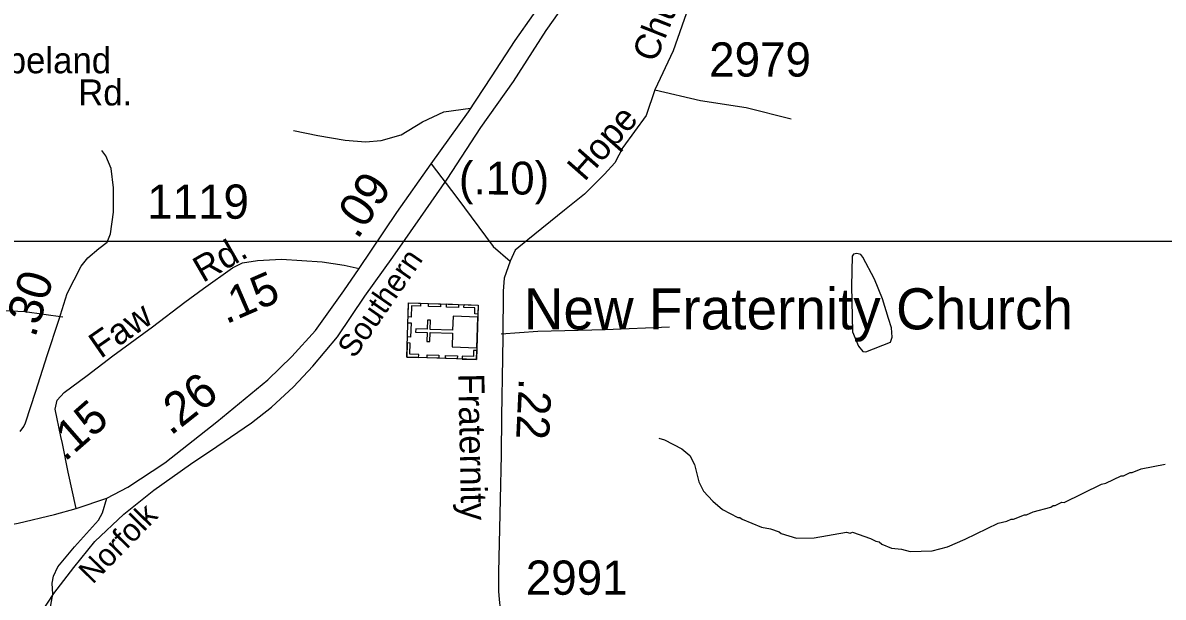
# Model space of a CAD drawing. Extents: x 1547597 to 1699558, y 810033 to 920809.
# Drawn here: x 1601176 to 1605342, y 830007 to 832105 of the extents above; entities that cross this region are included whole.
import ezdxf

# ---------------------------------------------------------------- set-up
doc = ezdxf.new("R2010")
doc.units = 0
for name, color, linetype in [('Exist Cultural Church with Cemetery CELL', 7, 'Continuous'), ('Exist Cultural Church with Cemetery Label', 7, 'Continuous'), ('Exist Hydrographic Misc Water Feature', 7, 'Continuous'), ('Exist Railroad Mainline', 7, 'Continuous'), ('Exist Railroad Mainline Label', 7, 'Continuous'), ('Exist Road Non-System Type 51', 7, 'Continuous'), ('Exist Road Primary US Mileage Hundredths English Label', 7, 'Continuous'), ('Exist Road Primary US UnDivided 4 Lane Attributed', 7, 'Continuous'), ('Exist Road Secondary Mileage Hundredths English Label', 7, 'Continuous'), ('Exist Road Secondary Type 41 Attributed', 7, 'Continuous'), ('Exist Road Secondary Type 51 Attributed', 7, 'Continuous'), ('Exist Road Secondary Type 51 Label', 7, 'Continuous'), ('Exist Road Secondary Type 51 Number Label', 7, 'Continuous'), ('Map Preparation Inset Cut Line', 7, 'Continuous')]:
    doc.layers.add(name, color=color, linetype=linetype)

msp = doc.modelspace()

# ---------------------------------------------------------------- linework, layer by layer
at = {"layer": 'Exist Cultural Church with Cemetery CELL'}
for points in [[(1602578.8, 830883.5), (1602585.4, 831082.5), (1602839.9, 831074), (1602833.2, 830875)], [(1602628.7, 831081.1), (1602628.4, 831069.8), (1602596.2, 831070.8), (1602594.8, 831030.3), (1602583.7, 831030.7), (1602585.4, 831082.5)], [(1602701.4, 831067.3), (1602658.1, 831068.7), (1602658.5, 831080.1), (1602701.8, 831078.7)], [(1602767.3, 831065), (1602724, 831066.5), (1602724.4, 831077.9), (1602767.7, 831076.4)], [(1602838.8, 831040.9), (1602827.3, 831041.3), (1602828, 831063.3), (1602787.6, 831064.6), (1602788, 831075.7), (1602839.9, 831074)], [(1602834.6, 830918.1), (1602838.4, 831030.2), (1602747.9, 831033.2), (1602746.2, 830982.5), (1602664.7, 830985.2), (1602665.8, 831018.2), (1602654.8, 831018.5), (1602653.7, 830985.6), (1602611.5, 830987), (1602611.1, 830975.4), (1602653.3, 830973.9), (1602652.2, 830940.9), (1602663.2, 830940.5), (1602664.3, 830973.6), (1602745.8, 830970.9), (1602744.1, 830921.1)], [(1602581.2, 830957.5), (1602583, 831009.3), (1602594.4, 831009), (1602592.6, 830957.2)], [(1602622, 830882.1), (1602622.4, 830893.4), (1602590.2, 830894.5), (1602591.6, 830935), (1602580.5, 830935.4), (1602578.8, 830883.5)], [(1602834.3, 830908.1), (1602822.8, 830908.5), (1602822.1, 830886.5), (1602781.7, 830887.8), (1602781.3, 830876.7), (1602833.2, 830875)], [(1602696.2, 830879.6), (1602652.9, 830881), (1602653.3, 830892.4), (1602696.5, 830891)], [(1602763.3, 830877.3), (1602720.1, 830878.8), (1602720.4, 830890.1), (1602763.7, 830888.7)]]:
    msp.add_lwpolyline(points, close=True, dxfattribs=at)
at = {"layer": 'Exist Hydrographic Misc Water Feature'}
for points in [[(1604207.3, 830976), (1604228.7, 830923.3), (1604244.9, 830904.5), (1604255.7, 830902.7), (1604345.6, 830937.8), (1604351.9, 830956.3), (1604349, 830990.8), (1604339, 831025.3), (1604316.8, 831096.1), (1604287, 831168.6), (1604244.8, 831249.4), (1604237.2, 831258.7), (1604222.5, 831262.2), (1604211, 831260.1), (1604206, 831252.5), (1604203.1, 831142.7), (1604207.3, 830976)], [(1603499.8, 830587.9), (1603519.7, 830581.7), (1603583.2, 830548.8), (1603612.9, 830524.4), (1603630.4, 830492.1), (1603645.5, 830427.9), (1603663, 830393.7), (1603696.6, 830357.2), (1603732.1, 830326.7), (1603787.7, 830298), (1603795.7, 830297.9), (1603803.6, 830291.8), (1603875.2, 830262.8), (1603907, 830256.3), (1603938.8, 830245.9), (1603946.8, 830239.8), (1604002.5, 830223), (1604066.5, 830224.1), (1604184.7, 830244.5), (1604198.6, 830240.3), (1604206.7, 830244.1), (1604272.3, 830221.2), (1604292.1, 830211), (1604304.1, 830208.8), (1604314.1, 830200.7), (1604349.9, 830186.2), (1604385.7, 830181.7), (1604417.6, 830173.2), (1604497.6, 830176.1), (1604553.8, 830191.3), (1604618.1, 830218.4), (1604738.8, 830276.7), (1604770.9, 830284.3), (1604787, 830292), (1604795, 830291.9), (1604835.2, 830307.4), (1604843.2, 830307.3), (1604867.3, 830318.9), (1604931.5, 830336), (1604939.6, 830341.9), (1604947.6, 830341.8), (1604971.8, 830353.4), (1604979.8, 830353.3), (1605116.5, 830419.4), (1605132.5, 830423.2), (1605188.9, 830450.4), (1605196.9, 830450.3), (1605221, 830462), (1605229, 830461.9), (1605261.2, 830475.4), (1605349.4, 830492.2)]]:
    msp.add_lwpolyline(points, dxfattribs=at)
at = {"layer": 'Exist Railroad Mainline'}
msp.add_lwpolyline([(1601147.7, 829804.9), (1601289.9, 830019.8), (1601362.5, 830115.8), (1601439.7, 830210.4), (1601544.8, 830309.9), (1601655.3, 830397.6), (1601789.2, 830492.5), (1601884.5, 830557.6), (1602011.6, 830643.8), (1602084.2, 830700.6), (1602165.1, 830775.4), (1602236.2, 830850.3), (1602326.2, 830957.4), (1602425.5, 831105.9), (1602527.3, 831248.5), (1602629.1, 831393.3), (1602726.8, 831533.8), (1602849, 831722.3), (1602968.9, 831890.7), (1603087.4, 832077), (1603182.9, 832211.8)], dxfattribs=at)
at = {"layer": 'Exist Road Non-System Type 51'}
for points in [[(1603484.7, 831860.1), (1603652.4, 831820.6), (1603819.1, 831795.4), (1603982.7, 831754.5)], [(1602164.5, 831711.1), (1602254.2, 831693.9), (1602353.9, 831676.7), (1602427.8, 831669.8), (1602485.7, 831675), (1602557.8, 831696.1), (1602636.4, 831743), (1602714.7, 831780), (1602811.6, 831792.6)], [(1600788.8, 831061.8), (1600950.9, 831061.8), (1601183.4, 831050.1), (1601322.8, 831030.4)], [(1602924, 830969.1), (1603057.5, 830978), (1603303.3, 830984.8), (1603539, 830993.9)], [(1601224.1, 829868.9), (1601275.6, 829964.9), (1601286.1, 830017.9), (1601283.1, 830057.6), (1601287.7, 830084.1), (1601304.3, 830117.3), (1601364.8, 830190.7), (1601452.6, 830288.3), (1601466.9, 830314.8), (1601483.6, 830368.5)]]:
    msp.add_lwpolyline(points, dxfattribs=at)
at = {"layer": 'Exist Road Primary US UnDivided 4 Lane Attributed'}
for points in [[(1602667.7, 831590.4), (1602803.7, 831779.6), (1602888.3, 831908.2), (1602975.1, 832040.5), (1603109.1, 832231.2)], [(1602404.3, 831206.9), (1602541.9, 831412.4), (1602667.7, 831590.4)], [(1601371.1, 830330.4), (1601483.6, 830368.5), (1601560, 830408.6), (1601694.4, 830497.4), (1601884.5, 830647.7), (1602071.1, 830800.8), (1602158.9, 830885.9), (1602244.9, 830980.5), (1602349.2, 831126.4), (1602404.3, 831206.9)], [(1600849.1, 830212.4), (1601078.6, 830262.9), (1601159.2, 830276.7), (1601291.4, 830308.7), (1601371.1, 830330.4)]]:
    msp.add_lwpolyline(points, dxfattribs=at)
at = {"layer": 'Exist Road Secondary Type 41 Attributed'}
msp.add_lwpolyline([(1601165.9, 830612.4), (1601180.1, 830630.5), (1601185.5, 830643.7), (1601223.3, 830759.3), (1601264.8, 830890.2), (1601307.4, 831018.2), (1601338.1, 831115.8), (1601389.2, 831216.4), (1601413.7, 831246.7), (1601454.4, 831281.1), (1601484.3, 831303.8), (1601496.1, 831333.7), (1601507.9, 831412.9), (1601507.9, 831501.6), (1601498.8, 831572.3), (1601478.9, 831619.4), (1601465.1, 831638.1)], dxfattribs=at)
at = {"layer": 'Exist Road Secondary Type 51 Attributed'}
for points in [[(1603608.3, 832161.5), (1603551.5, 832003.1), (1603484.7, 831860.1), (1603452.9, 831766.9), (1603368.4, 831649.1), (1603339.3, 831593.9), (1603301.5, 831552.6), (1603227.7, 831479.6), (1603155.5, 831420.4), (1603021.3, 831311.8), (1602975.2, 831274.1), (1602956.2, 831234.2)], [(1602667.7, 831590.4), (1602762.1, 831466.8), (1602894.4, 831288.1), (1602956.2, 831234.2)], [(1601650, 830995), (1601767.7, 831084.7), (1601836.5, 831134.1), (1601941.6, 831209.6), (1601978.7, 831228.6), (1602033.6, 831237.1), (1602120.9, 831241.3), (1602270.3, 831231.3), (1602350, 831219.6), (1602404.3, 831206.9)], [(1602956.2, 831234.2), (1602934.8, 831172.4), (1602930.5, 831124.9), (1602929.6, 830957.4), (1602928.3, 830880.6), (1602924.9, 830667.1), (1602923.2, 830527.1), (1602920.2, 830363.1), (1602916.7, 830204.2), (1602914.1, 830097.7), (1602914.1, 830029.4), (1602916.3, 829998.5), (1602920.2, 829964.2), (1602928.3, 829931.5)], [(1601371.1, 830330.4), (1601341.2, 830463.5), (1601321, 830568.1), (1601314.6, 830593.7), (1601294, 830693.2), (1601301.4, 830726.5), (1601326.8, 830754.6), (1601411, 830816.2), (1601505.1, 830888.2), (1601650, 830995)]]:
    msp.add_lwpolyline(points, dxfattribs=at)
at = {"layer": 'Map Preparation Inset Cut Line'}
for points in [[(1633724, 874749.3), (1571208, 874749.3), (1571208, 831307.2), (1633724, 831307.2)], [(1575502.6, 831307.2), (1641328.6, 831307.2), (1641328.6, 811336.3), (1575502.6, 811336.3)]]:
    msp.add_lwpolyline(points, close=True, dxfattribs=at)

# ---------------------------------------------------------------- texts
at = {"layer": 'Exist Cultural Church with Cemetery Label'}
msp.add_text('New Fraternity Church', height=150, dxfattribs=at).set_placement((1603006.3, 830985.1))
at = {"layer": 'Exist Railroad Mainline Label'}
for s, rotation, p in [('Southern', 55.3001, (1602387.3, 830875.7)), ('Norfolk', 45.6197, (1601430.9, 830051.8))]:
    msp.add_text(s, height=82.02, rotation=rotation, dxfattribs=at).set_placement(p)
at = {"layer": 'Exist Road Primary US Mileage Hundredths English Label'}
for s, rotation, p in [('.09', 56.1936, (1602398.4, 831310.4)), ('.26', 38.3255, (1601716.1, 830594.3))]:
    msp.add_text(s, height=125, rotation=rotation, dxfattribs=at).set_placement(p)
at = {"layer": 'Exist Road Secondary Mileage Hundredths English Label'}
for s, height, rotation, p in [('(.10)', 120, 359.8656, (1602769.1, 831478.1)), ('.30', 125, 72.5338, (1601220.9, 830951.7)), ('.15', 120, 23.3505, (1601918.6, 831003.2)), ('.22', 120, 267.3774, (1602988.6, 830808.3)), ('.15', 120, 41.2094, (1601329.5, 830499.4))]:
    msp.add_text(s, height=height, rotation=rotation, dxfattribs=at).set_placement(p)
at = {"layer": 'Exist Road Secondary Type 51 Label'}
for s, rotation, p in [('Church', 68.3435, (1603487.9, 831956.4)), ('Hope', 48.6742, (1603228.1, 831522.3)), ('Rd.', 29.9581, (1601833.8, 831154)), ('Faw', 34.6919, (1601460.4, 830876.3)), ('Fraternity', 271.1564, (1602766.9, 830823.3))]:
    msp.add_text(s, height=95, rotation=rotation, dxfattribs=at).set_placement(p)
for s, p in [('Copeland', (1600954.9, 831920.5)), ('Rd.', (1601378.4, 831803.1))]:
    msp.add_text(s, height=95, dxfattribs=at).set_placement(p)
at = {"layer": 'Exist Road Secondary Type 51 Number Label'}
for s, p in [('2979', (1603683.5, 831908.5)), ('1119', (1601630.3, 831389.3)), ('2991', (1603013.6, 830015.8))]:
    msp.add_text(s, height=125, dxfattribs=at).set_placement(p)

doc.saveas('drawing.dxf')
